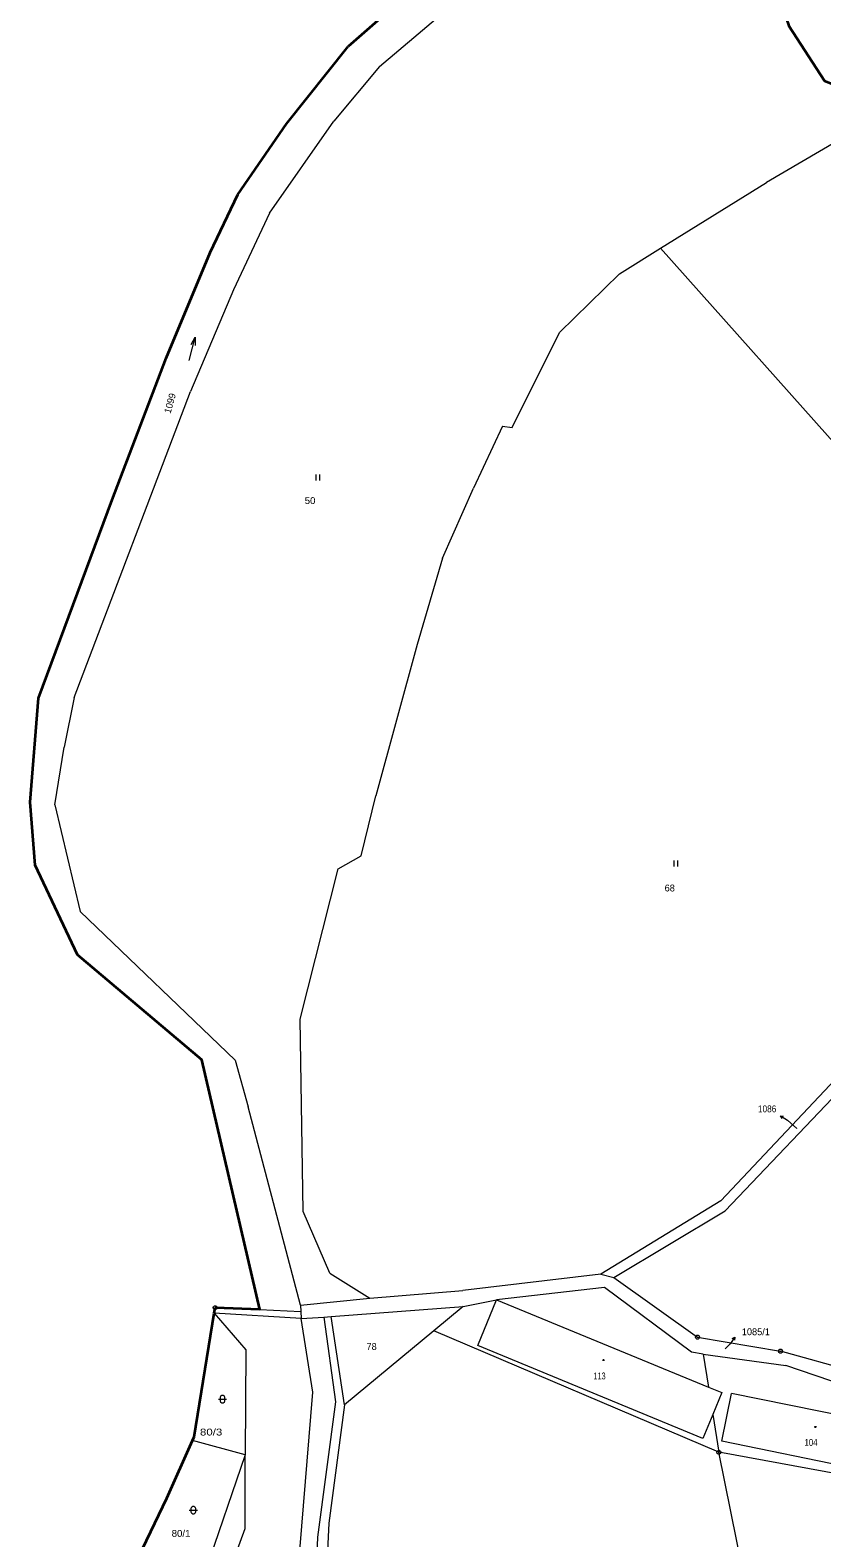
# Model space of a CAD drawing. Extents: x -687390 to -684106, y -954833 to -951648.
# Drawn here: x -687260.8 to -687064.8, y -952746.6 to -952373.7 of the extents above; entities that cross this region are included whole.
import ezdxf
from ezdxf.enums import TextEntityAlignment as Align

# ---------------------------------------------------------------- set-up
doc = ezdxf.new("R2010")
doc.units = 0
doc.header["$LTSCALE"] = 0.68
for name, color, linetype, lineweight in [('1', 7, 'Continuous', 13), ('3', 7, 'Continuous', 13), ('4', 7, 'Continuous', 13), ('5', 7, 'Continuous', 13), ('7', 7, 'Continuous', 13), ('8', 7, 'Continuous', 13)]:
    doc.layers.add(name, color=color, linetype=linetype, lineweight=lineweight)
doc.layers.add('2', color=7, linetype='Continuous')

msp = doc.modelspace()

# ---------------------------------------------------------------- linework, layer by layer
at = {"layer": '1', "lineweight": 35}
for p, q in [((-687151.09, -952350.57), (-687182.11, -952377.71)), ((-687220.18, -952721.66), (-687215.21, -952691.08)), ((-687215.21, -952691.08), (-687215.01, -952689.7)), ((-687203.95, -952690.15), (-687215.01, -952689.7))]:
    msp.add_line(p, q, dxfattribs=at)
at = {"layer": '1'}
for p, q in [((-687174.29, -952382.64), (-687150.92, -952362.86)), ((-687174.29, -952382.64), (-687185.61, -952396.18)), ((-687201.57, -952418.92), (-687185.61, -952396.18)), ((-687054.93, -952397.52), (-687078.55, -952411.32)), ((-687201.57, -952418.92), (-687210.42, -952437.92)), ((-687104.75, -952427.63), (-687044.76, -952494.97)), ((-687210.42, -952437.92), (-687221.11, -952463.07)), ((-687249.92, -952538.77), (-687221.11, -952463.07)), ((-687143.85, -952471.59), (-687151.09, -952486.96)), ((-687158.72, -952504.24), (-687151.09, -952486.96)), ((-687158.72, -952504.24), (-687165.02, -952525.65)), ((-687165.02, -952525.65), (-687175.23, -952563.1)), ((-687249.92, -952538.77), (-687252.36, -952551.04)), ((-687254.63, -952565.31), (-687252.36, -952551.04)), ((-687178.89, -952577.92), (-687175.23, -952563.1)), ((-687089.87, -952663.24), (-687060.17, -952631.78)), ((-687193.91, -952689.12), (-687206.82, -952639.99)), ((-687089.87, -952663.24), (-687119.52, -952681.38)), ((-687186.62, -952681.17), (-687176.72, -952687.33)), ((-687119.52, -952681.38), (-687153.71, -952685.44)), ((-687116.32, -952682.25), (-687095.59, -952697)), ((-687153.64, -952689.45), (-687145.34, -952687.72)), ((-687118.62, -952684.68), (-687145.34, -952687.72)), ((-687203.95, -952690.15), (-687193.82, -952690.64)), ((-687186.29, -952691.92), (-687153.64, -952689.45)), ((-687188.1, -952692.03), (-687185.17, -952712.96)), ((-687182.97, -952713.74), (-687186.29, -952691.92)), ((-687090.35, -952725.48), (-687160.85, -952695.43)), ((-687095.59, -952697), (-687075.09, -952700.47)), ((-687094.21, -952701.19), (-687073.73, -952704.01)), ((-687094.21, -952701.19), (-687092.92, -952709.35)), ((-687049.94, -952707.42), (-687075.09, -952700.47)), ((-687092.92, -952709.35), (-687089.6, -952710.71)), ((-687182.97, -952713.74), (-687186.84, -952742.99)), ((-687089.6, -952710.71), (-687091.84, -952716.13)), ((-687091.84, -952716.13), (-687090.35, -952725.48)), ((-687207.6, -952726.13), (-687220.6, -952722.6)), ((-687044.3, -952733.87), (-687090.35, -952725.48)), ((-687069.88, -952826.59), (-687090.35, -952725.48)), ((-687186.84, -952742.99), (-687189.26, -952791.65))]:
    msp.add_line(p, q, dxfattribs=at)
at = {"layer": '1', "lineweight": 35}
for points in [[(-687098.29, -952347.95), (-687092.6, -952348.56), (-687078.11, -952357.72), (-687073.06, -952372.61), (-687064.2, -952386.23), (-687053.17, -952390.55), (-687043.01, -952392.96)], [(-687203.95, -952690.15), (-687218.27, -952628.36), (-687249.05, -952602.4), (-687259.54, -952580.22), (-687260.78, -952564.65), (-687258.73, -952538.88), (-687240.47, -952489.83), (-687227.09, -952454.8), (-687216.23, -952428.63), (-687209.38, -952414.32), (-687197.34, -952396.79), (-687182.11, -952377.71)], [(-687226.98, -952736.85), (-687220.6, -952722.6), (-687220.18, -952721.66)], [(-687239.28, -952762.42), (-687235.97, -952755.55), (-687226.98, -952736.85)]]:
    msp.add_lwpolyline(points, dxfattribs=at)
at = {"layer": '1'}
for points in [[(-687114.94, -952433.97), (-687104.75, -952427.63), (-687078.55, -952411.32)], [(-687143.85, -952471.59), (-687141.47, -952471.96), (-687129.79, -952448.47), (-687114.94, -952433.97)], [(-687119.52, -952681.38), (-687116.32, -952682.25), (-687088.8, -952665.73), (-687057.31, -952632.73), (-686983.25, -952563.16)], [(-687254.63, -952565.31), (-687248.43, -952591.7), (-687210, -952628.47), (-687206.82, -952639.99)], [(-687186.62, -952681.17), (-687193.22, -952665.94), (-687193.96, -952618.36), (-687184.55, -952581.16), (-687178.89, -952577.92)], [(-687193.91, -952689.12), (-687176.72, -952687.33), (-687153.71, -952685.44)], [(-687094.21, -952701.19), (-687097.09, -952700.73), (-687118.62, -952684.68)], [(-687215.21, -952691.08), (-687207.42, -952700.15), (-687207.6, -952726.13)], [(-687193.91, -952689.12), (-687193.82, -952690.64), (-687193.72, -952692.37)], [(-687153.64, -952689.45), (-687160.85, -952695.43), (-687182.97, -952713.74)], [(-687199.73, -952765.59), (-687194.07, -952749.75), (-687190.86, -952710.62), (-687193.72, -952692.37)], [(-687193.72, -952692.37), (-687188.1, -952692.03), (-687186.29, -952691.92)], [(-687044.3, -952733.87), (-687040.61, -952715.33), (-687073.73, -952704.01)], [(-687185.17, -952712.96), (-687189.67, -952746.47), (-687192.16, -952809.95), (-687202.25, -952882.05), (-687200.5, -952891.91), (-687197.93, -952890.51)], [(-687213.7, -952761.02), (-687207.6, -952744.29), (-687207.6, -952726.13)]]:
    msp.add_lwpolyline(points, dxfattribs=at)
at = {"layer": '3'}
for p, q in [((-687221.429, -952455.408), (-687219.951, -952449.592)), ((-687190.09, -952483.55), (-687190.09, -952485.05)), ((-687189.09, -952485.05), (-687189.09, -952483.55)), ((-687101.49, -952579.07), (-687101.49, -952580.57)), ((-687100.49, -952580.57), (-687100.49, -952579.07))]:
    msp.add_line(p, q, dxfattribs=at)
for points in [[(-687220.928, -952451.408), (-687219.951, -952449.592), (-687219.959, -952451.654)], [(-687214.15, -952712.34), (-687212.88, -952712.34), (-687212.15, -952712.34)], [(-687221.4, -952739.79), (-687220.13, -952739.79), (-687219.4, -952739.79)]]:
    msp.add_lwpolyline(points, dxfattribs=at)
for points in [[(-687213.65, -952711.84), (-687213.55, -952711.55), (-687213.3, -952711.37), (-687212.99, -952711.37), (-687212.74, -952711.55), (-687212.64, -952711.84), (-687212.64, -952712.84), (-687212.74, -952713.13), (-687212.99, -952713.31), (-687213.3, -952713.31), (-687213.55, -952713.13), (-687213.65, -952712.84)], [(-687220.9, -952739.29), (-687220.8, -952739), (-687220.55, -952738.82), (-687220.24, -952738.82), (-687219.99, -952739), (-687219.89, -952739.29), (-687219.89, -952740.29), (-687219.99, -952740.58), (-687220.24, -952740.76), (-687220.55, -952740.76), (-687220.8, -952740.58), (-687220.9, -952740.29)]]:
    msp.add_lwpolyline(points, close=True, dxfattribs=at)
at = {"layer": '4'}
for p, q in [((-687145.34, -952687.72), (-687092.92, -952709.35)), ((-687193.72, -952692.37), (-687215.21, -952691.08)), ((-687089.64, -952722.76), (-687087.22, -952710.9)), ((-687091.84, -952716.13), (-687094.29, -952722.05)), ((-687045.97, -952731.65), (-687089.64, -952722.76)), ((-687207.6, -952726.13), (-687219.03, -952759.66))]:
    msp.add_line(p, q, dxfattribs=at)
for points in [[(-687094.29, -952722.05), (-687150.01, -952699.05), (-687145.34, -952687.72)], [(-687045.97, -952731.65), (-687043.56, -952719.79), (-687087.22, -952710.9)]]:
    msp.add_lwpolyline(points, dxfattribs=at)
at = {"layer": '5'}
for points in [[(-687118.78, -952702.51), (-687118.69, -952702.66), (-687118.78, -952702.81), (-687118.96, -952702.81), (-687119.05, -952702.66), (-687118.96, -952702.51)], [(-687066.36, -952719.06), (-687066.27, -952719.21), (-687066.36, -952719.36), (-687066.54, -952719.36), (-687066.63, -952719.21), (-687066.54, -952719.06)]]:
    msp.add_lwpolyline(points, close=True, dxfattribs=at)
at = {"layer": '7'}
for p, q in [((-687075.065, -952642.244), (-687073.38, -952643.34)), ((-687071.06, -952645.37), (-687073.38, -952643.34)), ((-687088.81, -952699.88), (-687087.56, -952698.64)), ((-687086.353, -952697.033), (-687087.56, -952698.64))]:
    msp.add_line(p, q, dxfattribs=at)
for points in [[(-687074.686, -952642.89), (-687075.065, -952642.244), (-687074.321, -952642.328)], [(-687087.023, -952697.367), (-687086.353, -952697.033), (-687086.487, -952697.77)]]:
    msp.add_lwpolyline(points, dxfattribs=at)
at = {"layer": '8'}
for p, q in [((-687215.13, -952689.7), (-687214.89, -952689.7)), ((-687095.71, -952697), (-687095.47, -952697)), ((-687075.21, -952700.47), (-687074.97, -952700.47)), ((-687090.47, -952725.48), (-687090.23, -952725.48))]:
    msp.add_line(p, q, dxfattribs=at)
for points in [[(-687214.86, -952689.22), (-687214.61, -952689.4), (-687214.51, -952689.69), (-687214.61, -952689.98), (-687214.86, -952690.16), (-687215.17, -952690.16), (-687215.42, -952689.98), (-687215.52, -952689.69), (-687215.42, -952689.4), (-687215.17, -952689.22)], [(-687095.44, -952696.52), (-687095.19, -952696.7), (-687095.09, -952696.99), (-687095.19, -952697.28), (-687095.44, -952697.46), (-687095.75, -952697.46), (-687096, -952697.28), (-687096.1, -952696.99), (-687096, -952696.7), (-687095.75, -952696.52)], [(-687074.94, -952699.99), (-687074.69, -952700.17), (-687074.59, -952700.46), (-687074.69, -952700.75), (-687074.94, -952700.93), (-687075.25, -952700.93), (-687075.5, -952700.75), (-687075.6, -952700.46), (-687075.5, -952700.17), (-687075.25, -952699.99)], [(-687090.2, -952725), (-687089.95, -952725.18), (-687089.85, -952725.47), (-687089.95, -952725.76), (-687090.2, -952725.94), (-687090.51, -952725.94), (-687090.76, -952725.76), (-687090.86, -952725.47), (-687090.76, -952725.18), (-687090.51, -952725)]]:
    msp.add_lwpolyline(points, close=True, dxfattribs=at)

# ---------------------------------------------------------------- texts
at = {"layer": '2'}
msp.add_text('1099', height=1.7, rotation=74.313, dxfattribs=at).set_placement((-687226.038, -952468.624))
for s, height, width, p in [('50', 1.7, 1.05, (-687192.835, -952490.9)), ('1086', 0.1, 0.9, (-687071.014, -952645.37)), ('113', 1.7, 0.7, (-687121.385, -952707.44)), ('80/3', 1.7, 1.25, (-687218.755, -952721.32)), ('104', 1.7, 0.85, (-687069.135, -952723.87)), ('80/1', 1.7, 1.05, (-687225.755, -952746.39))]:
    msp.add_text(s, height=height, dxfattribs=dict(at, width=width)).set_placement(p)
for s, height, p in [('68', 1.7, (-687103.756, -952586.73)), ('78', 1.7, (-687177.535, -952700.16)), ('1085/1', 0.1, (-687088.764, -952699.88))]:
    msp.add_text(s, height=height, dxfattribs=at).set_placement(p)
at = {"layer": '7', "width": 0.9}
msp.add_text('1086', height=1.7, dxfattribs=at).set_placement((-687076.116, -952641.37), align=Align.RIGHT)
at = {"layer": '7'}
msp.add_text('1085/1', height=1.7, dxfattribs=at).set_placement((-687084.655, -952696.51))

doc.saveas('drawing.dxf')
